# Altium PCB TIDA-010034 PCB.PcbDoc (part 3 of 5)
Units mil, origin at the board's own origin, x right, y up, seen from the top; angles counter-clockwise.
Board outline 4497.63 x 4881.81 mil, 4 copper layers (Top Layer, Signal Layer 1, Signal Layer 2, Bottom Layer), stack 62.18 mil thick; 483 components, 240 nets, 1255 pads, 589 vias.
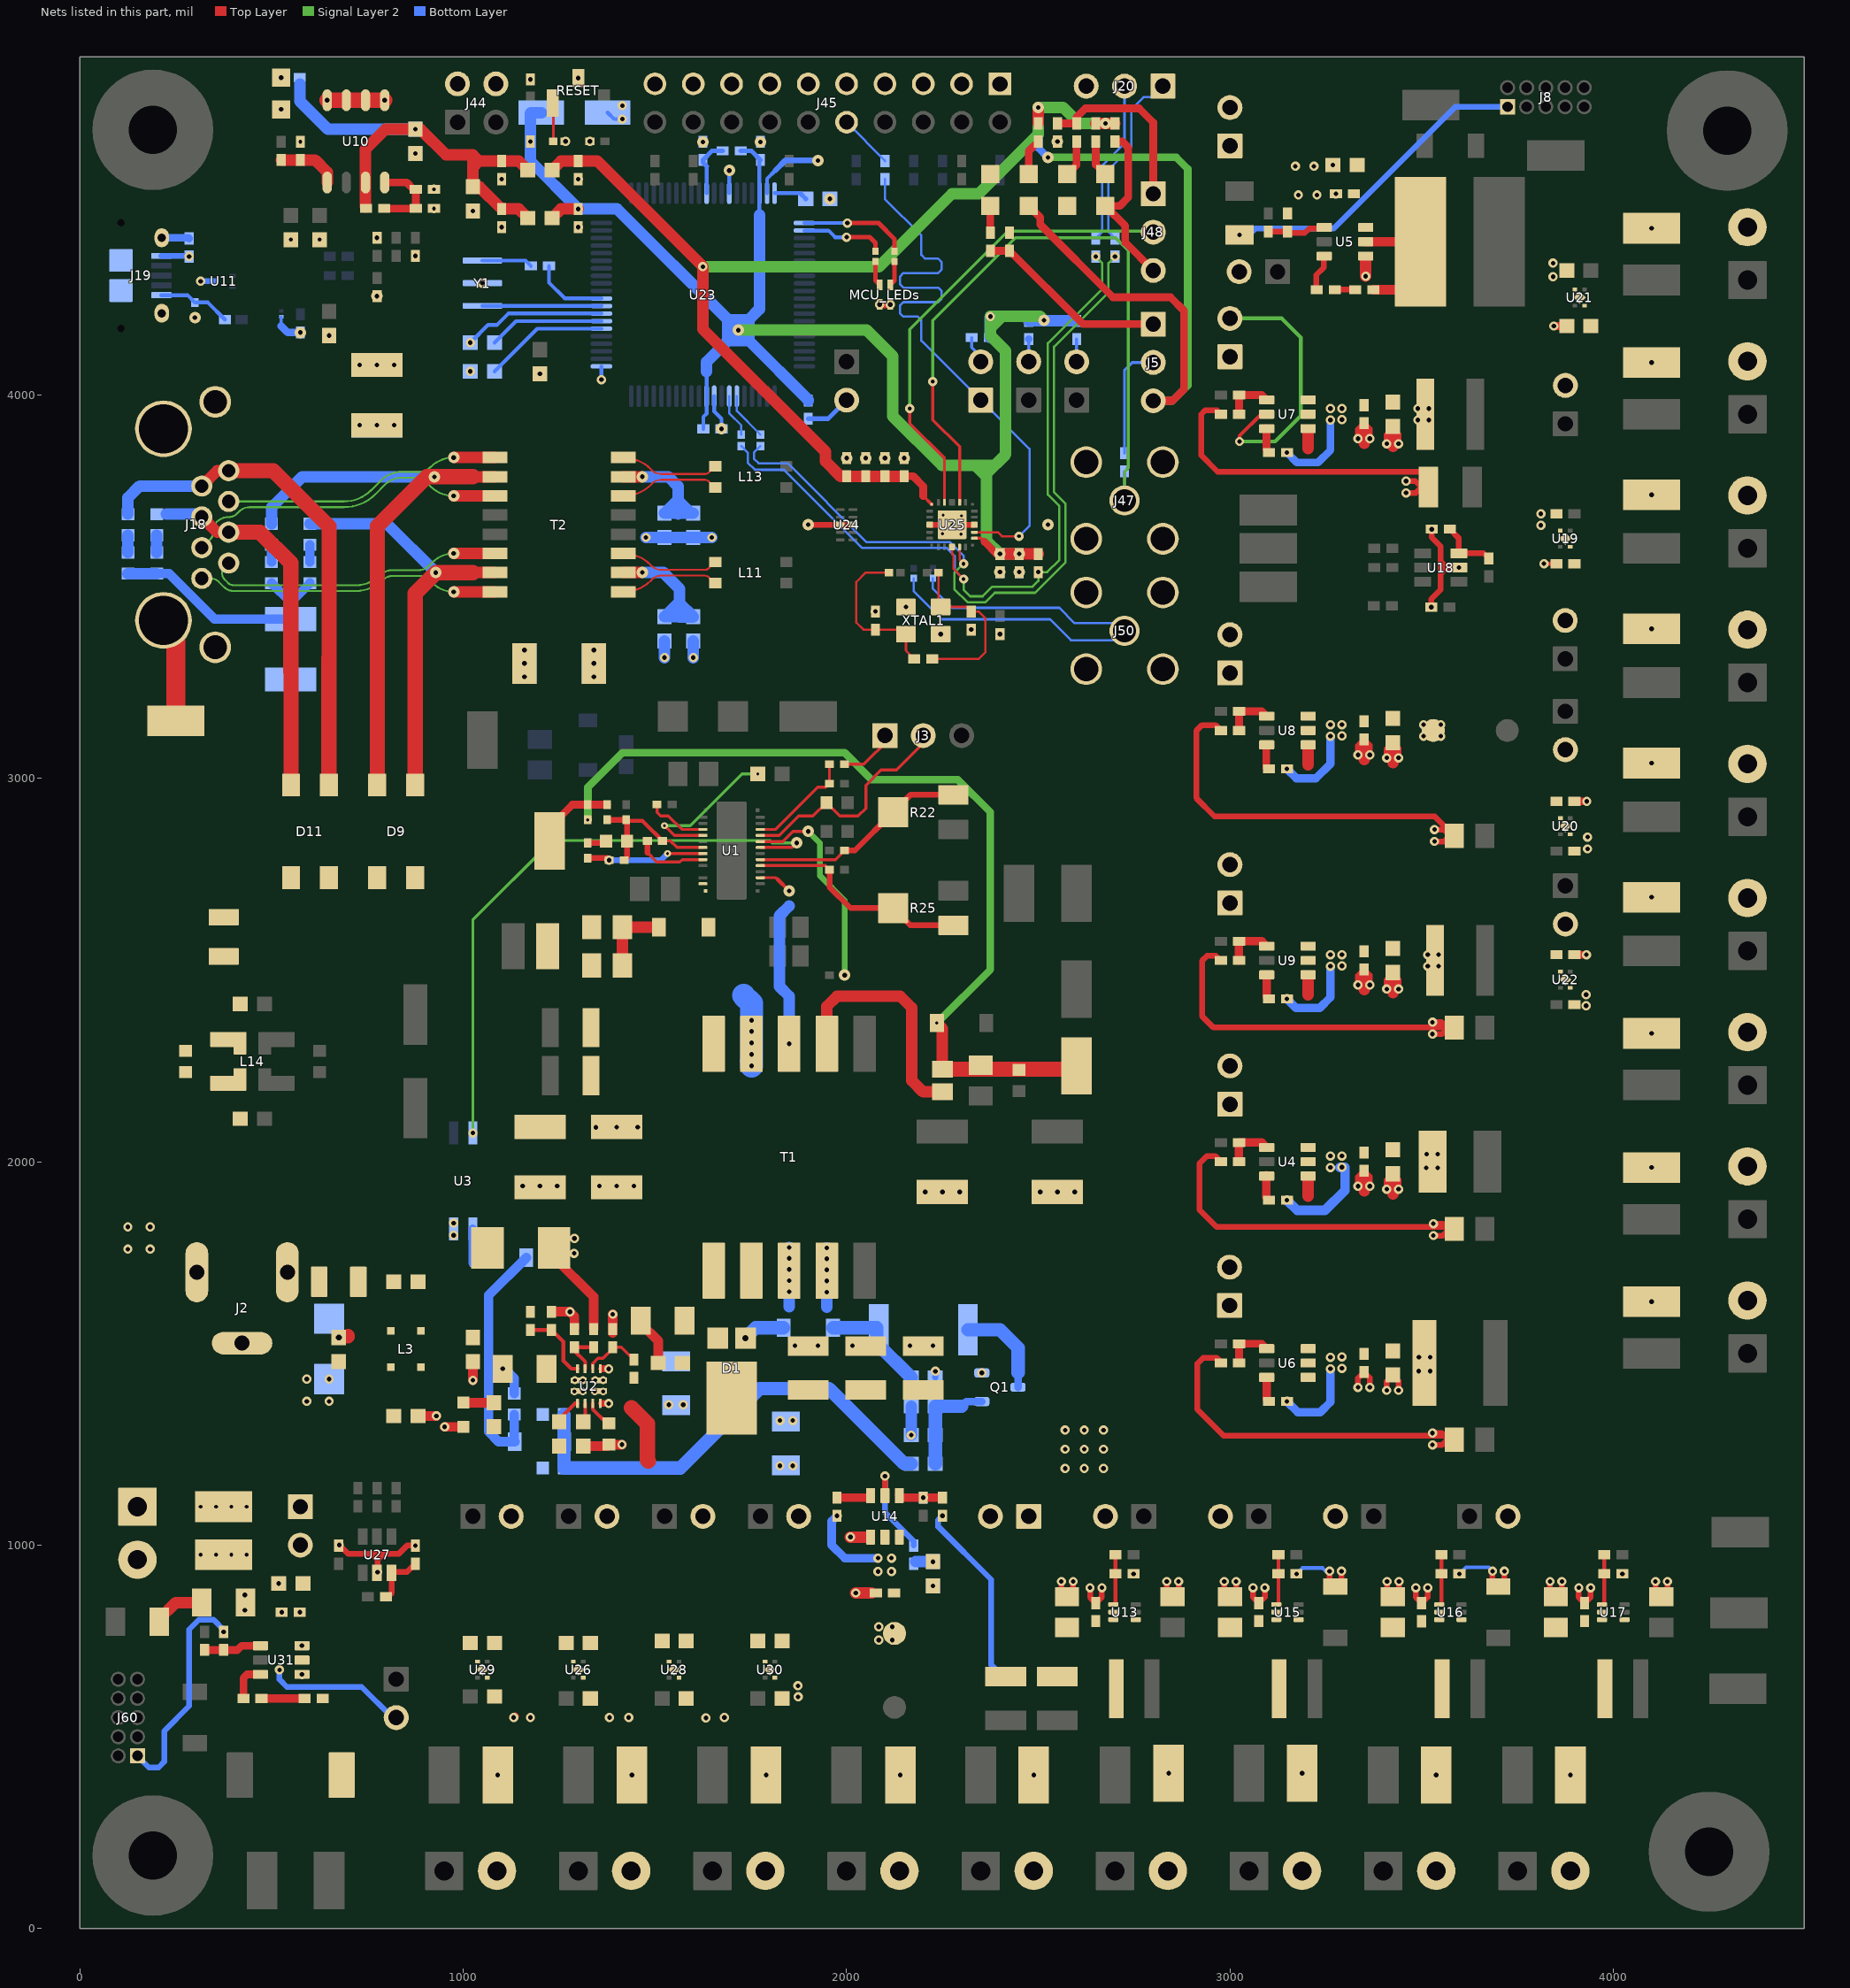
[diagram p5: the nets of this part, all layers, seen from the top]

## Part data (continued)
U2: library part CMP-0078351-3, "2.7V-22V, 4A, 50mohm Priority Power MUX, RUX0012A (VQFN-HR-12)", Alternate Manufacturer="Texas Instruments", Alternate PartNumber=TPS2121RUXT
U3: "Optocoupler, 3.75 kV, 80-160% CTR, SMT", Manufacturer="Fairchild Semiconductor", Supplier Part Number 1=HMHA2801A-ND, Voltage_Isolation_Vrms=3750V
U4: "4.5V to 17V Input, 2A Output, Synchronous SWIFT Step-Down Converter, DDC0006A (SOT-23-T-6)", Alternate Manufacturer="Texas Instruments", Alternate PartNumber=TPS562208DDCT
U5 U31: "4.5V to 28V Input Voltage, Synchronous Buck LED Driver, DDC0006A (SOT-23-T-6)", Alternate Manufacturer="Texas Instruments", Alternate PartNumber=TPS54201DDCT
U6: library part CMP-0013277-3, "4.5-V to 17-V Input, 2-A Synchronous Step-Down Voltage Regulator, DDC0006A (SOT-6)", Alternate Manufacturer="Texas Instruments", Alternate PartNumber=TPS561208DDCT
U7 U9: "4.5-V to 17-V Input, 2-A Synchronous Step-Down Voltage Regulator, DDC0006A (SOT-23-T-6)", Alternate Manufacturer="Texas Instruments", Alternate PartNumber=TPS561201DDCT
U8: "4.5V to 17V Input, 2A Output, Synchronous Step-Down Converter, DDC0006A (SOT-23-T-6)", Alternate Manufacturer="Texas Instruments"
U10: library part CMP-0036447-1, "Single Output Low Noise LDO, 500 mA, Adjustable 1.3 to 6.5 V Output, 2.5 to 16 V Input, 8-pin SOIC (D), -40 to 125 degC, Green (RoHS & no Sb/Br)", Manufacturer="Texas Instruments", Rating=Catalog
U11: "ESD Solution for Super-Speed (6 Gbps) USB 3.0 Interface, 2 Channels, -40 to +85 degC, 3-pin SOT (DRT), Green (Rohs & No Sb/Br)", Alternate Manufacturer="Texas Instruments", Alternate PartNumber=Equivalent, Breakdown Voltage(Min)(V)=9, Differential Capacitance(pF)=0.01, IO Capacitance(Typ)(pF)=0.7, IO Leakage Current(nA)=10, Supplier Part Number 1=296-25509-2-ND
U12: "ESD in 0402 Package with 10 pF Capacitance and 6 V Breakdown, 1 Channel, -40 to +125 degC, 2-pin X2SON (DPY), Green (RoHS & no Sb/Br)", Alternate Manufacturer="Texas Instruments", Alternate PartNumber=Equivalent, Breakdown Voltage(Min)(V)=6, IO Capacitance(Typ)(pF)=10, Supplier Part Number 1=296-30406-2-ND
U13 U17: "1-A High Efficiency Step-Down Converter in SOT Package, DRL0006A (SOT-OTHER-6)", Alternate Manufacturer="Texas Instruments", Alternate PartNumber=TLV62568DRLT
U14: "4.5-V TO 28-V INPUT, 2-A OUTPUT, EMI FRIENDLY SYNCHRONUOUS STEP-DOWN CONVERTOR, DDC0006A (SOT-23-T-6)", Alternate Manufacturer="Texas Instruments", Alternate PartNumber=TPS54202HDDCT
U15: library part CMP-0077789-1, "2-A High Efficiency Synchronous Buck Converter with Forced PWM Feature, DRL0006A (SOT-OTHER-6)", Alternate Manufacturer="Texas Instruments", Alternate PartNumber=TLV62569ADRLT
U16: library part CMP-0081125-1, "1-A High Efficiency Synchronous Buck Converter with Forced PWM Feature, DRL0006A (SOT-OTHER-6)", Alternate Manufacturer="Texas Instruments", Alternate PartNumber=TLV62568ADRLT
U18 U27: "Power Sequencer, 6-pin SOT-23, Pb-Free", Manufacturer="Texas Instruments", PackageTopMarking=F20A*XTT, PowerWise=N, Supplier Part Number 1=LM3880MF-1AATR-ND
U19 U26: library part CMP-0079107-2, "200-mA, Small Size, Low-Dropout Linear Voltage Regulator, DQN0004A (X2SON-4)", Alternate Manufacturer="Texas Instruments"
U20 U28: library part CMP-0079104-2, "200-mA, Small Size, Low-Dropout Linear Voltage Regulator, DQN0004A (X2SON-4)", Alternate Manufacturer="Texas Instruments"
U21 U29: library part CMP-0079101-2, "200-mA, Small Size, Low-Dropout Linear Voltage Regulator, DQN0004A (X2SON-4)", Alternate Manufacturer="Texas Instruments"
U22 U30: library part CMP-0079108-2, "200-mA, Small Size, Low-Dropout Linear Voltage Regulator, DQN0004A (X2SON-4)", Alternate Manufacturer="Texas Instruments"
U23: library part CMP-0038965-1, "25 MHz Mixed Signal Microcontroller with 128 KB Flash, 8192 B SRAM and 63 GPIOs, -40 to 85 degC, 80-pin QFP (PN), Green (RoHS & no Sb/Br)", Frequency(MHz)=25, Manufacturer="Texas Instruments", Temp Sensor=Yes
U24: library part CMP-0073613-3, "4-Channel Ultra-Low-Capacitance IEC ESD Protection Diode, DQA0010A (USON-10)", Alternate Manufacturer="Texas Instruments"
U25: library part CMP-0081932-1, "DP83825IRLLR, RLL0024A (VQFN-24)", Alternate Manufacturer="Texas Instruments", Alternate PartNumber=DP83825IRLLT
XTAL1: library part CMP-0079863-1, "Crystal, 25 MHz, 20 ppm, AEC-Q200 Grade 1, SMD", Frequency_Fixed=25MHz, Frequency Stability="50 ppm", Frequency Tolerance="20 ppm", Manufacturer="ECS Inc.", Supplier Part Number 1=XC2151CT-ND
Y1: library part CMP-0006148-5, "Resonator, 4 MHz, 1000 ppm, 39 pF, SMD", Frequency_Fixed=4MHz, Frequency Stability="800 ppm", Frequency Tolerance="1000 ppm", Load Capacitance="39 pF", Manufacturer=MuRata, Supplier Part Number 1=490-7861-1-ND
ZZ1: library part AssemblyNoteLabel
ZZ2 ZZ3 ZZ4: library part AssemblyNote

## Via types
v1: diameter 24, hole 12, Top Layer to Bottom Layer, 451 vias
v2: diameter 30, hole 12, Top Layer to Bottom Layer, 86 vias
v3: diameter 24, hole 10, Top Layer to Bottom Layer, 22 vias
v4: diameter 19.68, hole 7.87, Top Layer to Bottom Layer, 10 vias
v5: diameter 20, hole 10, Top Layer to Bottom Layer, 8 vias
v6: diameter 19.69, hole 7.87, Top Layer to Bottom Layer, 5 vias
v7: diameter 18, hole 7.5, Top Layer to Bottom Layer, 3 vias
v8: diameter 20, hole 8, Top Layer to Bottom Layer, 2 vias
v9: diameter 34, hole 16, Top Layer to Bottom Layer, 2 vias

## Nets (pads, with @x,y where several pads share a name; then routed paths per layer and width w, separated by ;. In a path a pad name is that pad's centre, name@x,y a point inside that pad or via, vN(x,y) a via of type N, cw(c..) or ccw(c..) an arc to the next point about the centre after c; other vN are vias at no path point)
3V3_IO_LDO: C73.1 C109.1 C110.2 C111.2 C117.2 C118.1 C121.1 C122.1 L17.2 R74.1 R77.1 R91.1 R106.2 R107.2 R109.2 R110.2 U23.18 U23.50 U25.19 | length 4481.7
  Top Layer w7.87: U25.19@2333.07,3626.38 2350.43,3626.38 2360,3616.81
  Top Layer w20: 2360,3616.81 2391.38,3585.43 v2(2400,3585.43)
  Top Layer w30: L17.2@1231.5,4461.81 1255.12,4485.43 v1(1300,4485.43) ; v2(2400,3585.43) v2(2450,3585.43) R91.1@2500,3585.43
  Signal Layer 2 w30: v2(1717.5,4169.31) 2052.5,4169.31 2120,4101.81 2120,3945 2248.19,3816.81 2335,3816.81 ; 2384.09,3816.81 2335,3816.81 ; v2(2450,3585.43) v2(2400,3585.43) 2365,3620.43 2365,3786.81 ; v2(2515,4195) 2505,4205 2405,4205 ; 2335,3816.81 2365,3786.81 ; 2365,3786.81 2365,3795 2415,3845 2415,4115 2375,4155 2375,4175 ; 2375,4175 v1(2375,4205) 2405,4205 ; 2375,4175 2405,4205
  Bottom Layer w10: C110.2@1626.38,3911.81 1626.38,3943.19 1634.84,3951.66 U23.50@1634.84,3997.05 1634.84,4061.66 ; 1772.64,4469.45 U23.18@1772.64,4526.58 C111.2@1772.64,4610.83
  Bottom Layer w12: R77.1@1723.62,4636.81 1751.38,4636.81 C111.2@1775,4613.19
  Bottom Layer w30: C109.1@1203.39,4736.81 1176.81,4736.81 1175,4735 v1(1175,4661.38) 1175,4610.43 v1(1300,4485.43) 1401.38,4485.43 1690,4196.81 ; 1634.84,4061.66 1634.84,4086.66 1690,4141.81 ; 1772.64,4469.45 1772.64,4224.45 1745,4196.81 ; R106.2@1900,3985.43 1900,3986.81 1745,4141.81 ; R110.2@2373.62,4150 2373.62,4203.62 v1(2375,4205) ; R109.2@2475,4193.62 R107.2@2600,4193.62 ; 1690,4141.81 v2(1717.5,4169.31) ; 1690,4141.81 1690,4196.81 ; 1690,4141.81 1745,4141.81 ; 1690,4196.81 v2@1715,4171.81 ; 1690,4196.81 1745,4196.81 ; v2@1715,4171.81 v2(1717.5,4169.31) ; v2@1715,4171.81 v2@1720,4171.81 ; v2(1717.5,4169.31) v2@1720,4171.81 ; v2(1717.5,4169.31) 1745,4141.81 ; v2@1720,4171.81 1745,4196.81 ; 1745,4141.81 1745,4196.81
3V3_VDD_LDO: C63.1 C115.2 C116.1 C119.1 C120.1 L16.2 R95.2 R96.2 R122.2 R123.2 U25.6 | length 2908.7
  Top Layer w8: 2200,3736.81 U25.6@2221.85,3714.96
  Top Layer w20: C115.2@2150,3788.19 2173.62,3788.19 2200,3761.81 2200,3736.81
  Top Layer w30: L16.2@1231.5,4586.81 1255.12,4610.43 C63.1@1300,4610.43 1349.57,4610.43 v1(1625,4335) 1625,4171.81 1945,3851.81 1945,3826.81 1983.62,3788.19 C116.1@2000,3788.19 C115.2@2150,3788.19 ; R122.2@2500,4708.62 v2(2500,4750) ; R95.2@2650,4708.62 v2(2675,4708.62) R96.2@2700,4708.62
  Signal Layer 2 w30: v1(1625,4335) 2085,4335 2275,4525 2345,4525 2500,4680 v2(2500,4750) 2565,4750 2606.38,4708.62 v2(2675,4708.62)
  Bottom Layer w30: R123.2@2500,4708.62 v2(2500,4750)
12V: 12V.1 J1.1 J4.1 J7.1 J10.1 J11.1 J14.1 J16.1 J23.1 J59.1 R4.2 R20.2 R131.2 U2.1 U2.8 | length 157.2
  Top Layer w40: 1438.87,1358 1480,1316.87 1480,1221.72 1482.72,1219
  other v1: 2570,1200 2620,1200 2670,1200 1826,1207 1859.73,1207 2570,1250 2620,1250 2670,1250 2570,1300 2620,1300 2670,1300
  other v3: 315,1100 355,1100 395,1100 435,1100
  other v5: 1290,1401 1312,1401 1343,1401 1365,1401
12V_Adapter: D5.1 R43.2 R44.2 R126.2 R132.1 U2.7 | length 254
  Top Layer w25: D5.1@1237.01,1775 1237.01,1750.49 1340,1647.5 R43.2@1340,1563.62
  other v1: 1289,1761 1289.76,1800
  other v5: 1291,1430 1312,1430
12V_PoE: C7.1 C8.1 C9.1 C10.1 D1.3 R128.2 R131.1 R132.2 U2.2
  other v1: 1826.29,1325 1859.73,1325 1536,1366 1574,1366
  other v5: 1344,1430 1365,1430
AUX_D: U1.7 U3.4 | length 1589.5
  Top Layer w7.8: U1.7@1774.8,2819.69 1857.87,2819.69 v2(1870,2831.81)
  Signal Layer 2 w7.8: v1(1025,2075) 1025,2631 1232,2838 1800,2838 1806.19,2831.81 v2(1870,2831.81)
Aux_Detect: C26.1 D7.1 R7.2 R29.2 | length 1210.4
  Bottom Layer w35: R29.2@1262.56,1201 1566,1201 1773,1408 1954,1408 2150.19,1211.81 R7.2@2168.5,1211.81 ; R29.2@1262.56,1203 C26.1@1262.56,1340.44
CLK_OUT: J47.1 R94.2 U25.2 | length 1849.1
  Top Layer w7.87: U25.2@2294.69,3719.88 2294.69,3865.31
  Top Layer w8: v3(2225,4035) 2225,3935 2294.69,3865.31
  Signal Layer 2 w7.87: v3(2225,4035) 2225,4195 2440,4410 2701.81,4410 2735,4376.81 2735,3810 2725,3800 J47.1@2725,3725
  Bottom Layer w7.87: J47.1@2725,3725 R94.2@2725,3801.38
CP: R19.2 T1.3 | length 380.3
  Bottom Layer w30: v2(1850,2307.58) 1850,2431.81 1825,2456.81 1825,2642.13 R19.2@1850,2667.13
CRS_DV: J53.1 R84.2 U25.20 | length 1601.1
  Top Layer w6: U25.20@2333.07,3642.13 2394.68,3642.13 2405,3631.81 v3(2450,3631.81)
  Bottom Layer w6: R84.2@2100,4563.19 2100,4511.81 2195,4416.81 2195,4375 2195,4365.53 2204.47,4356.06 2238.59,4356.06 2248.06,4346.59 2248.06,4327.66 2238.59,4318.19 2195,4318.19 2148.41,4318.19 2138.94,4308.72 2138.94,4289.78 2148.41,4280.31 2195,4280.31 2238.59,4280.31 2248.06,4270.85 2248.06,4251.91 2238.59,4242.44 2195,4242.44 2148.41,4242.44 2138.94,4232.97 2138.94,4214.04 2148.41,4204.57 2185.53,4204.57 2195,4195.1 2195,4178.94 2195,4141.81 J53.1@2350,3986.81 2477.19,3859.62 2477.19,3659 v3(2450,3631.81)
CRS_DV_S: J45.10 R84.1 | length 142.8
  Bottom Layer w6: J45.10@2000,4711.81 2100,4611.81 R84.1@2100,4610.43
DRAIN: D2.2 T1.1 U1.24 U1.A4
EARTH_GND: C57.1 C125.2 C126.2 EARTH.1 J18.9 J18.10 J18.11 J18.12 R101.1 R102.1 | length 278.5
  Top Layer w50: J18.11@217.91,3412.2 250,3380.12 EARTH.1@250,3147
  other v1: 1159.45,3265 1159.45,3300 1159.45,3335 730,3921.26 775,3921.26 820,3921.26
EXT_REF_CLK: J50.1 R108.1 R124.1 | length 1218.9
  Bottom Layer w6: R124.1@2175,3522.01 2175,3488.83 2248.83,3415 2531,3415 2585.37,3360.63 2700.63,3360.63 J50.1@2725,3385 2705,3405 2595,3405 2555,3445 2275,3445 2225,3495 R108.1@2225,3522.01
GND: +3.3V.2 +12V_PoE.1 C1.2 C2.2 C7.2 C8.2 C9.2 C12.1 C15.2 C20.2 C22.2 C26.2 C27.2 C28.2 C31.2 C33.2 C34.2 C35.2 C36.2 C37.2 C40.2 C41.2 C42.2 C43.2 C44.2 C45.2 C47.2 C48.2 C49.2 C51.2 C52.2 C53.2 C56.2 C62.2 C63.2 C64.2 C65.2 C66.2 C67.2 C68.2 C69.2 C70.2 C71.2 C72.2 C73.2 C74.2 C75.2 C77.2 C79.2 C80.2 C81.2 C82.2 C83.2 C84.2 C85.2 C86.2 C87.2 C88.2 C89.2 C90.2 C91.2 C92.2 C93.2 C94.2 C95.2 C96.2 C97.2 C98.2 C99.2 C100.2 C101.2 C102.2 C103.2 C104.1 C105.2 C106.2 C107.1 C108.2 C109.2 C110.1 C111.1 C112.1 C113.2 C114.2 C115.1 C116.2 C117.1 C118.2 C119.2 C120.2 C121.2 C122.2 C123.1 C124.1 C125.1 C126.1 C127.2 C128.2 C129.2 C130.2 C131.2 C132.2 C133.2 C134.2 C135.2 C136.2 C139.2 C140.2 C141.2 C142.2 D13.2 GND.1 J1.2 J6.2 J8.1 J9.2 J12.2 J13.2 J15.2 J17.2 J19.5 J20.3 J24.2 J25.2 J27.2 J29.2 J31.2 J34.2 J36.2 J39.2 J40.2 J43.2 J44.2 J44.4 J45.1 J45.3 J45.5 J45.7 J45.9 J45.11 J45.13 J45.15 J45.17 J45.19 J47.2 J47.3 J47.4 J47.5 J50.2 J50.3 J50.4 J50.5 J54.2 J55.2 J57.2 J58.2 J60.1 L3.2 L4.2 LED0_H.2 LED2_H.2 MCU_LEDs.3 MCU_LEDs.4 Q1.2 R9.1 R29.1 R32.1 R34.1 R37.1 R38.1 R40.1 R42.1 R52.1 R53.1 R54.2 R58.1 R59.1 R61.1 R63.1 R65.1 R76.2 R92.2 R93.1 R98.1 R101.2 R102.2 R103.1 R112.1 R117.1 R121.2 R125.1 R127.1 R129.1 R130.1 RESET.3 T1.7 T1.8 U2.3 U2.12 U3.2 U4.1 U5.1 U6.1 U7.1 U8.1 U9.1 U10.5 U10.6 U10.7 U10.8 U11.3 U12.2 U13.2 U14.1 U15.2 U16.2 U17.2 U18.2 U19.2 U19.5 U20.2 U20.5 U21.2 U21.5 U22.2 U22.5 U23.14 U23.19 U23.49 U23.61 U23.68 U24.3@2016.44,3661.81 U24.8@1983.56,3661.81 U25.9 U25.21 U25.25 U26.2 U26.5 U27.2 U28.2 U28.5 U29.2 U29.5 U30.2 U30.5 U31.1 XTAL1.2 XTAL1.4 Y1.2 | length 13439.1
  Top Layer w10: v1@3819.24,3560 C97.2@3851.38,3560
  Top Layer w12: U2.12@1357.4,1369.41 1362.87,1369.41 ; U2.3@1357.4,1459.96 1362.87,1459.96
  Top Layer w15: v1(676.38,1000.43) 700,976.81 761.38,976.81 ; v1(776.38,929.57) 776.38,961.81 ; v1(875,998.62) 853.19,998.62 831.38,976.81 791.38,976.81 ; v2(1900,3661.81) U24.8@1983.56,3661.81 U24.3@2016.44,3661.81 ; U25.9@2216.93,3661.81 v6(2275,3661.81) U25.21@2333.07,3661.81 ; v1(2560,905) 2560,880 C79.2@2575,865 2591,881 v1(2591,905) ; v1(2635,888.62) 2635,863.62 C80.2@2650,848.62 2666,864.62 v1(2666,888.62) ; v1(2835,905) 2835,880 C77.2@2850,865 2866,881 v1(2866,905) ; R37.1@2976.38,1475 2976.38,1477.62 2966,1488 2930,1488 2915,1473 2915,1354 2984,1285 3559.7,1285 ; R32.1@2976.38,2000 2961.38,2015 2940,2015 2920,1995 2920,1875 2965,1830 C31.2@3563.09,1830 ; R42.1@2976.38,2525 2975,2525 2963,2537 2940,2537 2927,2524 2927,2380 2957,2350 C51.2@3566.3,2350 ; R40.1@2976.38,3125 2962.38,3139 2927,3139 2912,3124 2912,2949 2960,2901 3534,2901 C47.2@3585,2850 ; R38.1@2976.38,3950 2966.38,3960 2935,3960 2925,3950 2925,3843 2968,3800 C43.2@3500,3800 ; v1(2985,905) 2985,880 C87.2@3000,865 3016,881 v1(3016,905) ; v1(3060,888.62) 3060,863.62 C88.2@3075,848.62 3091,864.62 v1(3091,888.62) ; v1(3260,931.93) 3260,906.93 C86.2@3275,891.93 3291,907.93 v1(3291,931.93) ; v1(3334,1411.38) 3334,1435.38 C42.2@3350,1451.38 3365,1436.38 v1(3365,1411.38) ; v1(3334,1936.38) 3334,1960.38 C34.2@3350,1976.38 3365,1961.38 v1(3365,1936.38) ; v1(3334,2461.38) 3334,2485.38 C53.2@3350,2501.38 3365,2486.38 v1(3365,2461.38) ; v1(3334,3061.38) 3334,3085.38 C49.2@3350,3101.38 3365,3086.38 v1(3365,3061.38) ; v1(3334,3886.38) 3334,3910.38 C45.2@3350,3926.38 3365,3911.38 v1(3365,3886.38) ; v1(3409,1403.5) 3409,1427.5 C41.2@3425,1443.5 3440,1428.5 v1(3440,1403.5) ; v1(3409,1928.5) 3409,1952.5 C33.2@3425,1968.5 3440,1953.5 v1(3440,1928.5) ; v1(3409,2450.57) 3409,2474.57 3425,2490.57 3440,2475.57 v1(3440,2450.57) ; v1(3409,3053.5) 3409,3077.5 C48.2@3425,3093.5 3440,3078.5 v1(3440,3053.5) ; v1(3409,3872.77) 3409,3896.77 3425,3912.77 3440,3897.77 v1(3440,3872.77) ; v1(3410,905) 3410,880 C90.2@3425,865 3441,881 v1(3441,905) ; v1(3459.61,3744.8) 3484.61,3744.8 3499.61,3759.8 3483.61,3775.8 v1(3459.61,3775.8) ; v1(3485,888.62) 3485,863.62 C91.2@3500,848.62 3516,864.62 v1(3516,888.62) ; C43.2@3500,3785 3517.91,3767.09 C43.2@3517.91,3760 ; v1(3525.39,3446.81) 3525.39,3467.98 3550,3492.58 3550,3535 ; v1(3526.38,3650) 3526.38,3628.62 3550,3605 3550,3565 ; v1(3528.3,2333) 3553.3,2333 3568.3,2348 C51.2@3566.3,2350 ; v1(3528.3,2364) 3552.3,2364 C51.2@3566.3,2350 ; v1(3528.36,1261.33) 3553.36,1261.33 3568.36,1276.33 3559.7,1285 ; v1(3528.36,1292.33) 3552.36,1292.33 3559.7,1285 ; v1(3530.67,1807.42) 3555.67,1807.42 3570.67,1822.42 C31.2@3563.09,1830 ; v1(3530.67,1838.42) 3554.67,1838.42 C31.2@3563.09,1830 ; v1(3533.62,2835.59) 3558.62,2835.59 3573.62,2850.59 3557.62,2866.59 v1(3533.62,2866.59) ; C40.2@3585,1275 3580,1275 3570,1285 3559.7,1285 ; C31.2@3585,1825 3585,1840 3575,1830 C31.2@3563.09,1830 ; C51.2@3585,2350 C51.2@3566.3,2350 ; v1(3597.24,3550) 3565,3550 ; v1(3685,931.93) 3685,906.93 C89.2@3700,891.93 3716,907.93 v1(3716,931.93) ; v1(3835,905) 3835,880 C93.2@3850,865 3866,881 v1(3866,905) ; v1(3910,888.62) 3910,863.62 C94.2@3925,848.62 3941,864.62 v1(3941,888.62) ; v1(4110,905) 4110,880 C92.2@4125,865 4141,881 v1(4141,905) ; 761.38,976.81 776.38,961.81 ; 761.38,976.81 791.38,976.81 ; 776.38,961.81 791.38,976.81 ; 3550,3535 3550,3565 ; 3550,3535 3565,3550 ; 3550,3565 3565,3550
  Top Layer w18: 1362.87,1369.41 1379.09,1369.41 v1(1379.37,1369.14) ; 1362.87,1459.96 1379.09,1459.96 v1(1379.37,1459.69)
  Top Layer w20: v1(1131.5,550) v1@1135,553.5 ; U14.1@2051.13,1020.87 U14.1@2062.6,1020.87 ; C85.2@2064.91,875 C85.2@2076.38,875 ; v1(2086.22,4236.22) v1(2113.78,4236.22) ; U4.1@3204.13,1951.13 U4.1@3204.13,1962.6 ; U9.1@3204.13,2476.13 U9.1@3204.13,2487.6 ; U8.1@3204.13,3076.13 U8.1@3204.13,3087.6 ; U7.1@3204.13,3901.13 U7.1@3204.13,3912.6 ; C34.2@3350,1964.91 C34.2@3350,1976.38 ; C53.2@3350,2489.91 C53.2@3350,2501.38 ; C49.2@3350,3089.91 C49.2@3350,3101.38 ; C45.2@3350,3914.91 C45.2@3350,3926.38 ; U5.1@3354.13,4351.13 U5.1@3354.13,4362.6 ; C33.2@3425,1957.04 C33.2@3425,1968.5 ; C52.2@3425,2482.04 3425,2490.57 C52.2@3425,2493.5 ; C48.2@3425,3082.04 C48.2@3425,3093.5 ; C44.2@3425,3907.04 3425,3912.77 C44.2@3425,3918.5 ; v1(3819.17,3560.06) v1@3819.24,3560 ; v1(3845,4180) C101.2@3877.14,4180 ; C103.2@3898.62,2540 v1(3930,2540) ; C100.2@3898.62,2940 v1@3930.76,2940
  Top Layer w25: L4.2@881.5,1336.81 v1(930,1336.81) ; v1(951.5,1308.5) +12V_PoE.1@1000,1308.5 ; v1(1025,1430) C20.2@1025,1478.5 ; R129.1@1230,1608.62 v1(1278.5,1608.62) 1278.5,1607.5 1290,1596 R125.1@1290,1563.62 ; R127.1@1315,1258.5 1376.06,1258.5 C22.2@1380,1262.44 1380.44,1262 v1(1414,1262) ; R130.1@1390,1553.62 v1(1390,1602.13)
  Top Layer w30: v1(2010,1021) 2051,1021 U14.1@2051.13,1020.87 ; v1(2023.78,875.13) 2064.78,875.13 C85.2@2064.91,875 ; 3204,1910 3204,1951 U4.1@3204.13,1951.13 ; 3204,2435 3204,2476 U9.1@3204.13,2476.13 ; 3204,3035 3204,3076 U8.1@3204.13,3076.13 ; 3204,3860 3204,3901 U7.1@3204.13,3901.13 ; 3349.87,1923.78 3349.87,1964.78 C34.2@3350,1964.91 ; 3349.87,2448.78 3349.87,2489.78 C53.2@3350,2489.91 ; 3349.87,3048.78 3349.87,3089.78 C49.2@3350,3089.91 ; 3349.87,3873.78 3349.87,3914.78 C45.2@3350,3914.91 ; v1(3354,4310) 3354,4351 U5.1@3354.13,4351.13 ; 3424.87,1915.91 3424.87,1956.91 C33.2@3425,1957.04 ; 3424.87,2440.91 3424.87,2481.91 C52.2@3425,2482.04 ; 3424.87,3040.91 3424.87,3081.91 C48.2@3425,3082.04 ; 3424.87,3865.91 3424.87,3906.91 C44.2@3425,3907.04
  Top Layer w40: v1(645,4769.09) U10.7@695,4769.09 U10.6@745,4769.09 v1(795,4769.09)
  Bottom Layer w8: 525,4180 D13.2@525,4204.33
  Bottom Layer w10: v1(1018.5,4136.81) 1065,4183.31 1088.31,4183.31 1117.6,4212.6 U23.68@1360.24,4212.6 ; v1(1360.24,4040.24) U23.61@1360.24,4074.81 ; C109.2@1376.61,4736.81 1393.43,4720 v1(1415,4720) ; U23.49@1654.53,3997.05 1654.53,3957.28 1673.62,3938.19 v2(1673.62,3911.81) ; U23.14@1693.9,4526.58 v2(1693.9,4585.71) ; U23.19@1792.32,4526.58 1792.32,4564.14 1815,4586.81 ; v1(3173.62,925) 3188.62,940 3242,940 3250.07,931.93 v1(3260,931.93) ; v1(3598.62,925) 3615.63,942 3674.93,942 v1(3685,931.93)
  Bottom Layer w15: J60.1@150,450 179.92,420.08 204.92,420.08 220,435.16 220,515 285,580 285,780 310,805 348.74,805 375,778.74 v1(375,773.62) ; J19.5@212.4,4362.99 283.39,4362.99 v1(285,4361.38) ; v1(315,4296.81) U11.3@352.36,4296.81 ; v1(520.63,674.41) 520.63,649.33 539.96,630 735,630 815,550 J58.2@825,550 ; 1815,4586.81 1840,4611.81 v2(1925,4611.81) ; C12.1@2230,1438.31 C12.1@2231.5,1436.81 v1(2231.5,1453.5) ; v1(2250,1076.38) 2239,1065.38 2239,1048 2377,910 2377,688 2405,660 ; v1(3025,4417.91) 3050,4417.91 3066.09,4434 3270,4434 3587.81,4751.81 J8.1@3724.02,4751.81
  Bottom Layer w20: 525,4180 541.81,4163.19 v2(575,4163.19) ; v1(2140,400) 2140,434
  Bottom Layer w30: v1(1476.5,3628.5) C56.2@1525,3628.5 C74.2@1600,3628.5 v1(1648.5,3628.5) ; v1(1525,3315) C75.2@1525,3358.5 ; v1(1600,3315) C142.2@1600,3358.5 ; 1850,1621.58 v1(1850,1661) v1(1850,1690) v1(1850,1719) v1(1850,1748) v1(1850,1776) ; 1948,1620.3 v1(1948,1660) v1(1948,1689) v1(1948,1718) v1(1948,1747) v1(1948,1775) ; v1(2168.5,1286.81) R9.1@2168.5,1361.81
  other v1: 1090,400 1440,400 1790,400 2488,400 3538,400 3888,400 2840,405 3188,405 1633,549 1175,550 1381.5,550 1431.5,550 1681,550 1873.51,604 1873.14,633 579.13,662.6 526.38,825 430,830 430,870 2225,893.5 518.5,900 2748.62,925 4023.62,925 2352.76,1449.21 1865,1520 1925,1520 2015,1520 2165,1520 2225,1520 4100,1635 975,1808.27 975,1840 2205,1921.26 2250,1921.26 2295,1921.26 2505,1921.26 2550,1921.26 2595,1921.26 4100,1985 4100,2335 3929,2407 3929,2436 4100,2690 3933,2816 3933,2847 3930.83,2939.94 4100,3040 1340.55,3265 1340.55,3300 1340.55,3335 2400,3376.38 2325,3388.19 4100,3390 2075,3435.43 3811,3660 3811,3690 4100,3740 1018.5,4061.81 730,4078.74 775,4078.74 820,4078.74 4100,4085 1050,4291.81 3842.87,4308.57 3842.94,4344.06 875,4363.19 775,4410.43 4100,4435 1100,4438.19 1300,4438.19 1025,4480.32 3178.39,4521.81 3226.89,4521.81 3276.38,4525 1100,4563.19 1300,4563.19 3170.51,4596.81 3219.02,4596.81 3268.5,4600 875,4630.32 1266.96,4661.81 1330.32,4661.81 525,4745.47 1415,4755 1175,4823.62 1300,4826.77
  other v2: 1155,1936.81 1200,1936.81 1245,1936.81 1355,1937.01 1400,1937.01 1445,1937.01 2245.28,3376.38 2154.72,3447.24 2400,3538.19 2450,3538.19 2525,3661.81 2000,3835.43 2050,3835.43 2100,3835.43 2150,3835.43 1200,4055.32 650,4155.32 300,4202.13 775,4258.19 1956.5,4511.81 1625,4660.44 1775,4660.44 2550,4661.38
  other v3: 315,975 355,975 395,975 435,975 550,4405.32 625,4405.32 923.62,4486.81 923.62,4536.81 575,4660.43
  other v6: 2298.19,3636.81 2250,3638.62 2300,3685 2251.81,3686.81
LED_0: J48.2 U25.4 | length 1231.2
  Top Layer w7.87: v3(2165,3965) 2165,3925.32 2255.32,3835 U25.4@2255.32,3719.88
  Signal Layer 2 w7.87: v3(2165,3965) 2165,4171.81 2420.59,4427.41 2797.59,4427.41 J48.2@2800,4425
LED_2: J5.2 R94.1 | length 299.7
  Bottom Layer w7.87: R94.1@2725,3848.62 2725,4065 2745,4085 J5.2@2800,4085
MDC: R71.1 R89.1 U25.16 | length 2060.5
  Top Layer w6: U25.16@2294.69,3603.74 2294.69,3570.31 v3(2305,3560)
  Signal Layer 2 w6: v3(2305,3560) 2281.13,3536.13 2281.13,3493.87 2315.87,3459.13 2361.58,3459.13 2386.58,3484.13 2491.58,3484.13 2570.87,3563.42 2570.87,3716.58 2540.87,3746.58 2540.87,4125.87 2683,4268 2683,4344.38 v1(2700,4361.38)
  Bottom Layer w6: R71.1@1775,3866.85 1774.85,3866.85 1758,3850 1758,3833.81 1770,3821.81 1846.19,3821.81 2052,3616 2270,3616 2305,3581 v3(2305,3560)
MDC_EXT: J20.1 R89.2 | length 473.6
  Bottom Layer w6: R89.2@2700,4408.62 2683,4425.62 2683,4588 2743,4648 2743,4746 2774,4777 2802,4777 J20.1@2825,4800
MDC_OB: R71.2 U23.46 | length 125.7
  Bottom Layer w6: U23.46@1713.58,3997.05 1713.58,3958.19 R71.2@1775,3896.77
MDIO: R72.1 R90.1 R91.2 U25.15 | length 2064
  Top Layer w6: U25.15@2275,3603.74 2275,3585 2278.94,3581.06 2278.94,3546.06 v3(2305,3520)
  Signal Layer 2 w6: v3(2305,3520) 2305,3492.45 2322.45,3475 2355,3475 2380,3500 2485,3500 2500,3515 v1(2500,3538.19) 2523.19,3538.19 2555,3570 2555,3710 2525,3740 2525,4135 2667,4277 2667,4344.38 v1(2650,4361.38)
  Bottom Layer w6: R72.1@1725,3866.85 1742,3849.85 1742,3824 1761,3805 1836.81,3805 2040.81,3601 2261,3601 2282,3580 2282,3543 v3(2305,3520)
MDIO_EXT: J20.2 R90.2 | length 422.4
  Bottom Layer w6: R90.2@2650,4408.62 2667,4425.62 2667,4599 2725,4657 J20.2@2725,4800
MDIO_OB: R72.2 U23.47 | length 113.2
  Bottom Layer w6: U23.47@1693.9,3997.05 1693.9,3952.1 1725,3921 R72.2@1725,3896.77
MSP_XIN2: U23.69 Y1.3 | length 310.2
  Bottom Layer w10: Y1.3@1050,4232.29 U23.69@1360.24,4232.29
MSP_XOUT2: R73.2 U23.70 | length 197.3
  Bottom Layer w10: R73.2@1223.62,4336.81 1223.62,4293.19 1264.84,4251.97 U23.70@1360.24,4251.97
Net+3.3V_1: +3.3V.1 R51.1
  other v1: 525,4828.15
Net+12V_PoE_2: +12V_PoE.2 R4.1 | length 80
  Top Layer w25: +12V_PoE.2@1000,1371.5 R4.1@1080,1371.5
NetC1_1: C1.1 C2.1 C3.1 C5.1 C6.1 L1.2 R1.2 T1.2 | length 194
  Bottom Layer w60: 1731,2434 1751.58,2413.42 1751,2412.85 1752,2411.85 v1(1752,2369) v1(1752,2340) v1(1752,2310) v1(1752,2280) 1752,2263.73 1751,2262.73 1752,2261.73 v1(1752,2250)
  other v1: 1345.84,2089.42 1400,2090.55 1455,2090.44
NetC3_2: C3.2 D2.1 R1.1 | length 195.5
  Top Layer w30: C3.2@1415,2511.81 R1.1@1415,2611.81 D2.1@1510.53,2611.81
NetC10_2: C10.2 R2.2 | length 128.9
  Top Layer w25: R2.2@1462.91,1585 1462.91,1578.09 1508.5,1532.5 C10.2@1508.5,1475
NetC11_1: C11.1 D4.2 R3.1 R5.2 R14.2 VBIAS.1 | length 2324
  Top Layer w30: v8(2235.53,2361.81) 2250,2347.34 R3.1@2250,2241.34
  Top Layer w40: R3.1@2250,2241.34 2591.34,2241.34 VBIAS.1@2600,2250
  Signal Layer 2 w20: v8(1325,2892.13) 1325,2976.81 1415,3066.81 1995,3066.81 2065,2996.81 2290,2996.81 2375,2911.81 2375,2501.28 v8(2235.53,2361.81)
NetC12_2: C12.2 D3.1 R6.2 | length 281.5
  Bottom Layer w35: D3.1@1964.47,1566.81 2078.86,1566.81 2078.86,1526.46 C12.2@2168.5,1436.81
NetC15_1: C15.1 Q1.1 R7.1 R9.2 | length 305
  Bottom Layer w20: 2300,1361.81 2312.6,1374.41 Q1.1@2352.76,1374.41
  Bottom Layer w35: R7.1@2231.5,1211.81 C15.1@2231.5,1286.81 ; 2231.5,1258.31 R9.2@2231.5,1361.81 2300,1361.81
NetC17_1: C17.1 R16.2 U1.19 | length 309.5
  Top Layer w7.8: v7(1532.87,2803.94) U1.19@1625.2,2803.94
  Top Layer w15: R16.2@1325,2792.13 1375,2792.13 v1(1380.32,2786.81)
  Bottom Layer w15: v1(1380.32,2786.81) 1515.75,2786.81 v7(1532.87,2803.94)
NetC17_2: C17.2 C18.2 R15.1 R18.2 R21.2 U1.18 | length 386.5
  Top Layer w7.8: R18.2@1519.69,2836.81 1540,2836.81 1557.13,2819.69 U1.18@1625.2,2819.69
  Top Layer w10: R21.2@1427.56,2889.57 1467.24,2889.57 1497.28,2859.53 1497.46,2859.53 1519.69,2837.3 R18.2@1519.69,2836.81
  Top Layer w15: R15.1@1375,2892.13 R21.2@1425,2892.13 1427.56,2889.57 C18.2@1427.56,2836.81 1427.56,2794.69 C17.2@1419.69,2786.81
NetC18_1: C18.1 R16.1 | length 49.6
  Top Layer w15: R16.1@1325,2831.5 1367.13,2831.5 C18.1@1372.44,2836.81
NetC19_1: C19.1 D14.2 F1.1 L2.1 L3.4 | length 2.9
  Top Layer w35: 700,1543.31 700,1546.24
  other v9: 675,1541.5
NetC19_2: C19.2 D14.1 J2.2 J2.3 L3.1 L4.1
  other v1: 591.93,1375 650,1375 591.93,1433.07 650,1433.07 125,1771.93 183.07,1771.93 125,1830 183.07,1830
NetC20_1: C20.1 D5.2 L2.2 L3.3 R27.2 R126.1 | length 79.9
  Bottom Layer w25: v1(1102.91,1460) 1108,1460 1133.07,1434.93 R27.2@1133.07,1395.56
NetC22_1: C22.1 U2.11 | length 72.6
  Top Layer w10: U2.11@1337.72,1369.41 1337.72,1354.28 1374.44,1317.56 C22.1@1380,1317.56
NetC24_1: C24.1 J3.2 U1.9 | length 603.2
  Top Layer w7.8: U1.9@1774.8,2851.18 1824.37,2851.18 1875,2901.81 1912.44,2901.81 C24.1@1947.44,2936.81 1982.44,2901.81 2030,2901.81 2050,2921.81 2050,2981.81 2090,3021.81 2130,3021.81 J3.2@2210,3101.81
NetC29_1: C29.1 L5.1 U4.2 | length 257.1
  Bottom Layer w25: v1(3148.62,1900) 3175.62,1873 3248,1873 3300,1925 3300,1985 v1@3287,1985
  other v1: 3512,1984 3542,1984 3262,1985 3292,1986 3262,2015 3292,2015 3513,2020 3542,2020
NetC29_2: C29.2 U4.6 | length 66.3
  Top Layer w22: U4.6@3094.88,1964.41 U4.6@3094.88,1961.61 ; U4.6@3095.87,1962.6 U4.6@3094.88,1961.61 ; C29.2@3100.39,1901.81 3094.88,1907.32 U4.6@3094.88,1961.61
NetC30_1: C30.1 R31.1 | length 52.8
  Top Layer w15: C30.1@3273.62,4275 R31.1@3326.38,4275
NetC30_2: C30.2 U5.6 | length 95.7
  Top Layer w15: C30.2@3225.39,4271.81 3225.39,4313.19 3244.88,4332.68 U5.6@3244.88,4359.41
NetC33_1: C33.1 C34.1 J4.2 U4.3
NetC35_1: C35.1 C36.1 J7.2 U5.3
NetC37_1: C37.1 R33.1 U5.4 | length 150.4
  Top Layer w15: R33.1@3100,4426.38 C37.1@3150,4426.38 ; C37.1@3149.02,4423.19 3195.39,4423.19 3206.42,4434.21 U5.4@3244.88,4434.21
NetC38_1: C38.1 L7.1 U6.2 | length 222.7
  Bottom Layer w22: v1(3148.62,1375) 3176.62,1347 3236,1347 3262,1373 v1(3262,1460)
  other v1: 3492,1454 3522,1454 3292,1461 3262,1490 3493,1490 3522,1490 3292,1491
NetC38_2: C38.2 U6.6 | length 64.9
  Top Layer w22: U6.6@3095.87,1437.6 3095.87,1380.51 C38.2@3101.38,1375
NetC39_1: C39.1 L8.1 U7.2 | length 216.4
  Bottom Layer w20: v1(3148.62,3850) 3174.62,3824 3230,3824 3262,3856 v1(3262,3935)
  other v1: 3490,3935 3519,3935 3292,3936 3262,3965 3292,3965 3490,3965 3519,3965
NetC39_2: C39.2 U7.6 | length 120.6
  Top Layer w20: U7.6@3094.88,3914.41 C39.2@3094.88,3857.32 ; U7.6@3095.87,3912.6 3095.87,3858.31 C39.2@3094.88,3857.32 ; C39.2@3100.39,3851.81 C39.2@3094.88,3857.32
NetC41_1: C41.1 C42.1 J10.2 U6.3
NetC44_1: C44.1 C45.1 J11.2 U7.3 U7.5 | length 709.3
  Top Layer w10: v1@3025,3876 v1(3025,3879) 3025,3893.63 3081.37,3950 U7.5@3095.87,3950
  Signal Layer 2 w10: J11.2@3000,4200 3135,4200 3185,4150 3185,3946 3118,3879 v1(3025,3879)
NetC46_1: C46.1 L9.1 U8.2 | length 211.5
  Bottom Layer w22: v1(3148.62,3025) 3173.62,3000 3224,3000 3262,3038 v1(3262,3110)
  other v1: 3505,3110 3550,3110 3292,3111 3262,3140 3292,3140 3505,3140 3550,3140
NetC46_2: C46.2 U8.6 | length 57.1
  Top Layer w20: C46.2@3094.88,3027.32 U8.6@3094.88,3084.41
NetC48_1: C48.1 C49.1 J14.2 U8.3
NetC50_1: C50.1 L10.1 U9.2 | length 215.9
  Bottom Layer w22: v1(3148.62,2425) 3172.62,2401 3234,2401 3262,2429 v1(3262,2510)
  other v1: 3516,2510 3544,2510 3292,2511 3262,2540 3292,2540 3516,2540 3544,2540
NetC50_2: C50.2 U9.6 | length 64.9
  Top Layer w22: U9.6@3095.87,2487.6 3095.87,2430.51 C50.2@3101.38,2425
NetC52_1: C52.1 C53.1 J16.2 U9.3
NetC54_1: C54.1 F2.1 L12.1 L14.4 L14.@387.01,2318.9
NetC54_2: C54.2 D9.2 D11.2 L14.1 L14.@387.01,2204.72 L15.1
NetC56_1: C56.1 C74.1 T2.7 | length 398.3
  Top Layer w30: T2.7@1417.5,3786.81 1466.81,3786.81 v2(1467,3787)
  Bottom Layer w30: v2(1467,3787) 1467.19,3786.81 1535.19,3786.81 1560,3762 1560,3725 ; C74.1@1600,3691.5 C74.1@1593.5,3691.5 ; 1560,3691.5 1561.5,3691.5 ; 1560,3691.5 C56.1@1525,3691.5 1558.5,3725 1560,3725 ; 1560,3691.5 1560,3725 ; 1560,3691.5 1560,3690 1561.5,3691.5 ; 1560,3725 C74.1@1593.5,3691.5 ; 1561.5,3691.5 C74.1@1593.5,3691.5
NetC57_2: C57.2 R45.1 R46.1 R47.1 R48.1 | length 659.3
  Bottom Layer w25: R48.1@200,3534.25 232.56,3534.25 351.26,3415.55 C57.2@550,3415.55 550,3459.25 ; R45.1@500,3509.25 550,3459.25 ; R46.1@600,3509.25 550,3459.25
  Bottom Layer w30: R47.1@125,3534.25 R48.1@200,3534.25
NetC58_1: C58.1 D9.4 T2.10 | length 1535.6
  Top Layer w30: 1024.99,3786.81 T2.10@1082.5,3786.81
  Top Layer w40: D9.4@775.77,2982.87 775.77,3657.59 904.99,3786.81 1024.99,3786.81
  Bottom Layer w30: C58.1@500,3664.37 500,3706.81 580,3786.81 v2(925,3786.81)
NetC58_2: C58.2 R45.2 | length 44.9
  Bottom Layer w25: R45.2@500,3564.37 C58.2@500,3609.25
NetC59_1: C59.1 D9.3 T2.15 | length 1111.7
  Top Layer w30: 1024.99,3536.81 T2.15@1082.5,3536.81
  Top Layer w40: D9.3@874.2,2982.87 874.2,3482.59 v2(928.41,3536.81) 1024.99,3536.81
  Bottom Layer w30: C59.1@600,3664.37 800.85,3664.37 v2(928.41,3536.81)
NetC59_2: C59.2 R46.2 | length 44.9
  Bottom Layer w25: R46.2@600,3564.37 C59.2@600,3609.25
NetC60_1: C60.1 D11.3 J18.7 J18.8 | length 1331.2
  Top Layer w30: J18.7@317.91,3762.6 358.07,3802.76 J18.8@387.99,3802.76
  Top Layer w40: J18.8@387.99,3802.76 504.06,3802.76 650,3656.81 D11.3@649.21,2982.87
  Bottom Layer w30: C60.1@125,3689.37 125,3731.81 155.79,3762.6 J18.7@317.91,3762.6
NetC60_2: C60.2 R47.2 | length 44.9
  Bottom Layer w30: R47.2@125,3589.37 C60.2@125,3634.25
NetC61_1: C61.1 D11.4 J18.4 J18.5 | length 956.8
  Top Layer w30: J18.5@317.91,3682.28 358.07,3642.13 J18.4@387.99,3642.13
  Top Layer w40: J18.4@387.99,3642.13 469.69,3642.13 550,3561.81 D11.4@550.79,2982.87
  Bottom Layer w30: 225,3689.37 310.83,3689.37 J18.5@317.91,3682.28
NetC61_2: C61.2 R48.2 | length 44.9
  Bottom Layer w30: R48.2@200,3589.37 C61.2@200,3634.25
NetC62_1: C62.1 C66.1 C67.1 C68.1 C72.1 L16.1 L17.1 R50.2 R51.2 U10.3 | length 1304.2
  Top Layer w20: R50.2@746.38,4486.81 R50.2@746.38,4490.43
  Top Layer w30: R50.2@746.38,4490.43 745,4491.81 U10.3@745,4554.53 745,4641.81 796.5,4693.31 v1(875,4693.31) 888.5,4693.31 955,4626.81 1025,4626.81 ; L17.1@1168.5,4461.81 1144.88,4485.43 C72.1@1100,4485.43 1042.13,4543.31 C67.1@1025,4543.31 1025,4596.81 ; L16.1@1168.5,4586.81 1144.88,4610.43 C62.1@1100,4610.43 1041.38,4610.43 ; 1025,4596.81 1025,4626.81 ; 1025,4596.81 1027.76,4596.81 1041.38,4610.43 ; 1025,4626.81 1041.38,4610.43
  Bottom Layer w30: 573.62,4811.81 573.62,4766.73 647.05,4693.31 v1(875,4693.31)
NetC69_1: C69.1 R50.1 R53.2 U10.4 | length 221.5
  Top Layer w20: R50.1@793.62,4486.81 R53.2@876.38,4486.81 C69.1@876.38,4536.81 870,4536.81 852.28,4554.53 U10.4@795,4554.53
NetC75_1: C75.1 C142.1 T2.2 | length 456.9
  Top Layer w30: T2.2@1417.5,3536.81 1466.81,3536.81 v2(1467,3537)
  Bottom Layer w30: v2(1467,3537) 1467.19,3536.81 1521.95,3536.81 1563.76,3495 1563.76,3457.74 ; 1563.76,3421.5 1563.76,3457.74 ; 1563.76,3421.5 C142.1@1600,3421.5 ; 1563.76,3421.5 C75.1@1525,3421.5 1563.5,3460 1563.5,3457.99 1563.76,3457.74 ; 1563.76,3421.5 1563.76,3421.24 1599.74,3421.24 C142.1@1600,3421.5 ; 1563.76,3457.74 C142.1@1600,3421.5
NetC76_1: C76.1 L19.1 U14.2 | length 217.3
  Bottom Layer w22: v1(1975,1076.38) 1961,1062.38 1961,1000 1995,966 v1(2082,966)
  other v1: 2084,752 2119,752 2084,787 2119,787 2082,931 2117,931 2117,966
NetC76_2: C76.2 U14.6 | length 89.9
  Top Layer w22: C76.2@1975,1123.62 2057.09,1123.62 U14.6@2062.6,1129.13
NetC78_2: C78.2 R57.1 R59.2 U14.4 | length 113.9
  Top Layer w22: U14.4@2137.4,1129.13 2142.91,1123.62 C78.2@2199,1123.62 ; v1(2200,1123.62) R59.2@2250,1123.62
NetC79_1: C79.1 C80.1 J22.2 U13.3
NetC83_1: C83.1 C84.1 C85.1 J23.2 R55.1 U14.3 | length 52.1
  Bottom Layer w15: R55.1@2175,951.38 R55.1@2180.12,956.5
  Bottom Layer w30: R55.1@2180.12,956.5 v1(2225,956.5)
NetC87_1: C87.1 C88.1 J26.2 U15.3
NetC90_1: C90.1 C91.1 J28.2 U16.3
NetC93_1: C93.1 C94.1 J30.2 U17.3
NetC97_1: C97.1 J32.2 U19.4
NetC100_1: C100.1 J35.2 U20.4
NetC101_1: C101.1 J37.2 U21.4
NetC103_1: C103.1 J41.2 U22.4
NetC105_1: C105.1 U23.67 | length 302
  Bottom Layer w10: C105.1@1081.5,4136.81 1137.6,4192.92 U23.67@1360.24,4192.92
NetC106_1: C106.1 U23.20 | length 87.6
  Bottom Layer w10: U23.20@1812.01,4526.58 C106.1@1878.74,4526.58
  Bottom Layer w12: C106.1@1878.74,4526.58 C106.1@1893.5,4511.81
NetC108_1: C108.1 U23.66 | length 324.9
  Bottom Layer w10: C108.1@1081.5,4061.81 1192.92,4173.23 U23.66@1360.24,4173.23
NetC112_2: C112.2 R77.2 U23.11 | length 151.9
  Bottom Layer w10: U23.11@1634.84,4526.58 1634.84,4596.97
  Bottom Layer w12: 1634.84,4596.97 1625,4606.81 C112.2@1625,4613.19 1648.62,4636.81 R77.2@1676.38,4636.81
NetC124_2: C124.2 R100.1 R104.2 XTAL1.3 | length 416.3
  Top Layer w6: R100.1@2110.04,3536.81 2050,3536.81 2025,3511.81 2025,3406.81 2043.62,3388.19 C124.2@2075,3388.19 2142.91,3388.19 XTAL1.3@2154.72,3376.38 2154.72,3333.46 R104.2@2176.38,3311.81
NetC127_1: C127.1 R104.1 R105.1 XTAL1.1 | length 455.1
  Top Layer w6: R104.1@2223.62,3311.81 2345,3311.81 2361.81,3328.62 2361.81,3418.19 2344.57,3435.43 C127.1@2325,3435.43 2313.19,3447.24 XTAL1.1@2245.28,3447.24 2239.96,3452.56 R105.1@2239.96,3536.81
NetC130_1: C130.1 J33.2 U26.4
NetC133_1: C133.1 J42.2 U28.4
NetC134_1: C134.1 J38.2 U29.4
NetC136_1: C136.1 J56.2 U30.4
NetC137_1: C137.1 R118.1 | length 103.8
  Top Layer w22: C137.1@473.62,600 R118.1@577.19,600 ; R118.1@577.19,599.81 R118.1@577.38,599.81
NetC137_2: C137.2 U31.6 | length 101.6
  Top Layer w20: C137.2@426.38,600 426.38,653.19 435.79,662.6 U31.6@470.87,662.6
NetC139_1: C139.1 C140.1 J59.2 U31.3
  other v1: 579.13,737.4 573.62,825
NetC141_1: C141.1 R119.1 U31.4 | length 150.4
  Top Layer w20: R119.1@325,726.38 C141.1@375,726.38 410.73,726.38 421.75,737.4 U31.4@470.87,737.4
NetD1_1: D1.1 D1.2 D3.2 R2.1 T1.9 T1.10 | length 110.3
  Bottom Layer w35: v9(1736.22,1540.2) 1762.84,1566.81 D3.2@1835.53,1566.81
NetD7_2: D7.2 D8.1 R27.1 | length 643.3
  Bottom Layer w25: D7.2@1133.07,1271.26 R27.1@1133.07,1340.44 ; D7.2@1134.53,1269.8 1092.2,1269.8 1066,1296 1066,1651.53 D8.1@1164.47,1750
NetD8_2: D8.2 U3.1 | length 89.5
  Bottom Layer w22: D8.2@1025,1735.53 U3.1@1025,1825
NetD9_1: D9.1 D11.1 F2.2
NetD12_2: D12.2 J19.1 U12.1 | length 192.4
  Bottom Layer w10: J19.1@212.4,4260.63 280.87,4260.63 U12.1@300,4241.5 333.66,4241.5 D12.2@378.35,4196.81
NetF1_2: F1.2 J2.1
NetJ3_1: J3.1 R24.2 | length 142.2
  Top Layer w7.8: R24.2@1994.69,3036.81 2045,3036.81 J3.1@2110,3101.81
NetJ5_1: J5.1 R97.1 R103.2 | length 504.3
  Top Layer w20: R97.1@2375,4376.38 R103.2@2425,4376.38 2616.38,4185 J5.1@2800,4185
NetJ5_3: J5.3 LED2_L.2 R123.1 | length 1927.4
  Top Layer w20: LED2_L.2@2475,4493.66 2505,4463.66 2505,4445 2695,4255 2845,4255 2880,4220 2880,4015 2850,3985 J5.3@2800,3985
  Signal Layer 2 w20: v2(2525,4620) 2860,4620 2890,4590 2890,4025 2850,3985 J5.3@2800,3985
  Bottom Layer w20: R123.1@2500,4661.38 2500,4645 v2(2525,4620)
NetJ18_1: J18.1 T2.16 | length 798.3
  Top Layer w30: v2(974.99,3486.81) T2.16@1082.5,3486.81
  Signal Layer 2 w5: J18.1@317.91,3521.65 342.52,3521.65 cw(c342.52,3495.52) 361,3514 376,3499 ccw(c400.14,3523.14) 400.14,3489 720.64,3489 ccw(c720.64,3589.36) 791.61,3518.39 cw(c814.8,3495.2) 814.8,3528 888.13,3528 cw(c888.13,3496.13) 910.64,3518.69 ; 910.67,3518.67 919.56,3509.77 ccw(c974.99,3565.21) v2(974.99,3486.81)
NetJ18_2: J18.2 T2.14 | length 784.8
  Top Layer w30: v2(974.99,3586.81) T2.14@1082.5,3586.81
  Signal Layer 2 w5: J18.2@387.99,3561.81 379.05,3552.87 ccw(c404.29,3527.62) 370.62,3539.49 370.62,3536.33 ccw(c396.54,3536.33) 378.21,3518 386.11,3510.11 ccw(c400.85,3524.85) 400.85,3504 720.64,3504 ccw(c720.64,3589.36) 781,3529 cw(c814.8,3495.2) 814.8,3543 882.11,3543 ccw(c882.11,3583.11) 910.47,3554.75 919.58,3563.86 cw(c974.99,3508.45) v2(974.99,3586.81)
NetJ18_3: J18.3 T2.11 | length 856.6
  Top Layer w30: v2(974.99,3736.81) T2.11@1082.5,3736.81
  Signal Layer 2 w5: J18.3@317.91,3601.97 340.68,3624.73 ccw(c325.41,3640) 347,3640 347,3645.35 cw(c380.45,3645.35) 356.8,3669 cw(c387.88,3637.92) 387.88,3681.88 ccw(c387.88,3713.72) 410.39,3691.19 415.77,3696.58 ; 415.79,3696.6 cw(c442,3670.35) 442,3707.44 689.02,3707.44 ccw(c689.02,3822.44) 770.34,3741.12 795.61,3766.39 cw(c839.18,3722.82) 839.18,3784.44 879.82,3784.44 cw(c879.82,3756.27) 899.74,3776.19 913.75,3762.18 ccw(c974.99,3823.43) 914.49,3761.44 ccw(c974.99,3823.43) v2(974.99,3736.81)
NetJ18_6: J18.6 T2.9 | length 728.8
  Top Layer w30: v2(974.99,3836.81) T2.9@1082.5,3836.81
  Signal Layer 2 w5: J18.6@387.99,3722.44 689.02,3722.44 ccw(c689.02,3822.44) 759.73,3751.73 785,3777 cw(c839.18,3722.82) 839.18,3799.44 884,3799.44 ccw(c884,3842.29) 914.3,3811.99 914.49,3812.19 cw(c973.94,3752.73) 973.94,3836.81 v2(974.99,3836.81)
NetJ19_6: J19.6 J19.7 J19.8 J19.9 J19.10 J19.11 R54.1 | length 72.3
  Bottom Layer w20: J19.7@213.39,4410.24 283.39,4410.24 R54.1@285,4408.62
NetJ48_1: J48.1 R98.2 R99.1 | length 477.2
  Top Layer w20: R98.2@2550,4708.62 R99.1@2600,4708.62 2600,4725 2623,4748 2763,4748 2800,4711 J48.1@2800,4525
NetJ48_3: J48.3 LED0_L.2 R96.1 | length 461.1
  Top Layer w20: R96.1@2700,4661.38 2719.62,4661.38 2735,4646 2735,4516 2712.66,4493.66 LED0_L.2@2675,4493.66 2727,4441.66 2727,4398 J48.3@2800,4325
NetJ49_2: J49.2 R106.1 | length 120.1
  Bottom Layer w12: R106.1@1900,3938.19 1951.38,3938.19 J49.2@2000,3986.81
NetJ51_2: J51.2 R107.1 | length 59.6
  Bottom Layer w7.87: J51.2@2600,4086.81 R107.1@2600,4146.38
NetJ52_2: J52.2 R109.1 | length 59.6
  Bottom Layer w7.87: J52.2@2475,4086.81 R109.1@2475,4146.38
NetJ53_2: J53.2 R110.1 | length 73
  Bottom Layer w7.87: R110.1@2326.38,4150 2326.38,4123.62 2350,4100 J53.2@2350,4086.81
NetL6_1: L6.1 R31.2 U5.2 | length 348.4
  Top Layer w25: U5.2@3354.13,4400 3468.27,4400 L6.1@3471.46,4396.81 ; R31.2@3373.62,4275 3449.41,4275 3473.2,4251.2 3497.44,4275.44 L6.1@3497.44,4361.44
NetL11_1: L11.1 T2.3 | length 263.1
  Top Layer w5: T2.3@1417.5,3586.81 cw(c1417.5,3486.81) 1488.21,3557.52 ccw(c1515.89,3579.26) 1516.99,3544.08 ; T2.3@1442.86,3580 1453,3580 ; 1515.89,3544 1629.38,3544 ccw(c1629.19,3561.81) L11.1@1647,3562
NetL11_2: L11.2 T2.1 | length 290.5
  Top Layer w5: T2.1@1417.5,3486.81 T2.1@1418.68,3486.81 ; L11.2@1647,3509 ccw(c1628.69,3510.69) 1630.38,3529 1517,3529 ccw(c1515.95,3495.24) 1489.39,3516.1 cw(c1418.68,3586.81) 1453.04,3492.9 ; T2.1@1418.68,3486.81 ccw(c1418.68,3586.81) T2.1@1438.87,3488.87 ; T2.1@1418.68,3486.81 1436.81,3486.81 T2.1@1438.87,3488.87 ; T2.1@1438.87,3488.87 ccw(c1418.68,3586.81) 1453.04,3492.9 ; T2.1@1438.87,3488.87 1442.9,3492.9 1453.04,3492.9
NetL13_1: L13.1 T2.8 | length 263.4
  Top Layer w5: T2.8@1417.5,3836.81 cw(c1417.5,3736.81) 1488.21,3807.52 ccw(c1515.9,3829.26) 1516.99,3794.08 ; T2.8@1442.86,3830 1453,3830 ; 1515.9,3794 1629.38,3794 ccw(c1629.19,3811.81) L13.1@1647,3812 ; L13.1@1657.28,3814.57 L13.1@1657.48,3814.37
NetL13_2: L13.2 T2.6 | length 290.5
  Top Layer w5: T2.6@1417.5,3736.81 T2.6@1418.68,3736.81 ; L13.2@1647,3759 ccw(c1628.69,3760.69) 1630.38,3779 1517,3779 ccw(c1515.95,3745.24) 1489.39,3766.1 cw(c1418.68,3836.81) 1453.04,3742.9 ; T2.6@1418.68,3736.81 ccw(c1418.68,3836.81) T2.6@1438.87,3738.87 ; T2.6@1418.68,3736.81 1436.81,3736.81 T2.6@1438.87,3738.87 ; T2.6@1438.87,3738.87 ccw(c1418.68,3836.81) 1453.04,3742.9 ; T2.6@1438.87,3738.87 1442.9,3742.9 1453.04,3742.9
NetL18_1: L18.1 U13.4
NetL20_1: L20.1 R118.2 U31.2
NetL21_1: L21.1 U15.4
NetL22_1: L22.1 U16.4
NetL23_1: L23.1 U17.4
NetLED0_H_1: LED0_H.1 R99.2 | length 96.2
  Top Layer w20: LED0_H.1@2575,4576.34 2576.34,4576.34 2600,4600 R99.2@2600,4661.38
NetLED0_L_1: LED0_L.1 R95.1 | length 95.4
  Top Layer w20: R95.1@2650,4661.38 2650,4601.34 LED0_L.1@2675,4576.34
NetLED2_H_1: LED2_H.1 R97.2 | length 70
  Top Layer w20: R97.2@2375,4423.62 LED2_H.1@2375,4493.66
NetLED2_L_1: LED2_L.1 R122.1 | length 95.4
  Top Layer w20: LED2_L.1@2475,4576.34 2475,4636.38 R122.1@2500,4661.38
NetLoop_1: Loop.1 R14.1 R15.2 | length 209.7
  Top Layer w20: Loop.1@1225,2836.81 1225,2871.81 1284.69,2931.5 R14.1@1325,2931.5 R15.2@1375,2931.5
NetMCU_LEDs_1: MCU_LEDs.1 R70.1 | length 66.1
  Top Layer w12: MCU_LEDs.1@2113.78,4287.4 2125,4298.62 R70.1@2125,4348.82
NetMCU_LEDs_2: MCU_LEDs.2 R69.1 | length 66.1
  Top Layer w12: R69.1@2075,4348.82 2075,4298.62 MCU_LEDs.2@2086.22,4287.4
NetQ1_3: Q1.3 R6.1 | length 253.4
  Bottom Layer w20: Q1.3@2447.24,1411.81 2447.24,1449.57
  Bottom Layer w35: R6.1@2316.14,1561.81 2400,1561.81 2447.24,1514.57 2447.24,1449.57
NetR3_2: R3.2 T1.4 | length 624.9
  Top Layer w30: T1.4@1948.43,2307.58 1948.43,2405.24 1975,2431.81 2140,2431.81 2170,2401.81 2170,2211.81 2199.53,2182.28 R3.2@2250,2182.28
NetR12_2: R12.2 U1.15 | length 158.7
  Top Layer w7.8: R12.2@1505.32,2931.81 1505.32,2911.5 1515,2901.81 1535,2901.81 1569.88,2866.93 U1.15@1625.2,2866.93
NetR13_1: R13.1 U1.8 | length 550.5
  Top Layer w7.8: U1.8@1774.8,2835.43 1833.62,2835.43 1860,2861.81 v2(1900,2861.81)
  Signal Layer 2 w15: v2(1900,2861.81) 1930,2831.81 1930,2746.81 1995,2681.81 v2(1995,2486.81)
NetR17_2: R17.2 U1.16 | length 415.2
  Top Layer w7.8: v7@1520,2876.81 v7(1525,2876.81) 1550.63,2851.18 U1.16@1625.2,2851.18
  Signal Layer 2 w7.8: v7(1525,2876.81) 1591.77,2876.81 1726.77,3011.81 v7(1768.5,3011.81)
NetR18_1: R18.1 U1.20 | length 188.2
  Top Layer w7.8: 1480,2806.81 1505,2781.81 1565,2781.81 1571.38,2788.19 U1.20@1625.2,2788.19
  Top Layer w15: 1480,2806.81 R18.1@1480,2836.81
NetR19_1: R19.1 U1.2 | length 89.5
  Top Layer w7.8: U1.2@1774.8,2740.95 1815.55,2740.95 1819.69,2736.81
  Top Layer w10: 1819.69,2736.81 v2(1850,2706.5)
NetR20_1: R20.1 U2.9 | length 72
  Top Layer w10: R20.1@1250,1321.5 1250,1327.98 1291.43,1369.41 U2.9@1298.35,1369.41
NetR22_1: R22.1 R22.2 R23.2 U1.5 | length 573.9
  Top Layer w7.8: U1.5@1774.8,2788.19 1971.06,2788.19 R23.2@1994.69,2811.81
  Top Layer w15: R23.2@1994.69,2811.81 2021.26,2811.81 R22.2@2121.26,2911.81 2166.54,2957.09 R22.1@2278.74,2957.09
NetR24_1: R24.1 R28.2 U1.10 | length 280.2
  Top Layer w7.8: U1.10@1774.8,2866.93 1815.12,2866.93 1925,2976.81 1945.32,2976.81 R28.2@1955.32,2986.81 R24.1@1955.32,3036.81
NetR25_2: R25.2 R25.3 R26.1 U1.4 | length 595.1
  Top Layer w7.8: U1.4@1774.8,2772.44 1944.69,2772.44 R26.1@1955.32,2761.81
  Top Layer w10: R25.3@2278.47,2616.81 R25.3@2278.74,2616.54
  Top Layer w15: R26.1@1955.32,2761.81 1955.32,2716.5 2010,2661.81 R25.2@2121.26,2661.81 2166.26,2616.81 R25.3@2278.47,2616.81
NetR30_1: R30.1 R32.2 U4.4 | length 114.9
  Top Layer w22: R32.2@3023.62,2000 3023.62,2037.4 ; R30.1@3023.62,2050 3083.27,2050 U4.4@3095.87,2037.4
NetR35_1: R35.1 R37.2 U6.4 | length 127.5
  Top Layer w20: R37.2@3023.62,1475 R35.1@3023.62,1525 3083.27,1525 U6.4@3095.87,1512.4
NetR36_1: R36.1 R38.2 U7.4 | length 127.5
  Top Layer w20: R38.2@3023.62,3950 R36.1@3023.62,4000 3083.27,4000 U7.4@3095.87,3987.4
NetR39_1: R39.1 R40.2 U8.4 | length 127.5
  Top Layer w20: R40.2@3023.62,3125 R39.1@3023.62,3175 3083.27,3175 U8.4@3095.87,3162.4
NetR41_1: R41.1 R42.2 U9.4 | length 127.5
  Top Layer w22: R42.2@3023.62,2525 R41.1@3023.62,2575 3083.27,2575 U9.4@3095.87,2562.4
NetR43_1: R43.1 R125.2 U2.5 | length 116
  Top Layer w10: U2.5@1318.03,1459.96 1318.03,1478.35 1290,1506.38 1299.62,1516 1330.38,1516 R43.1@1340,1506.38
NetR44_1: R44.1 R129.2 U2.6 | length 194.3
  Top Layer w10: R44.1@1175,1561.38 R129.2@1230,1561.38 1261,1530.38 1261,1481 1282.04,1459.96 U2.6@1298.35,1459.96
NetR49_1: R49.1 R52.2 U10.1 | length 160.3
  Top Layer w30: R49.1@525,4613.19 R52.2@575,4613.19 613.62,4613.19 645,4581.81 U10.1@645,4554.53
NetR55_2: R55.2 U14.5 | length 263.3
  Top Layer w15: U14.5@2100,1129.13 v1(2100,1180)
  Bottom Layer w15: v1(2100,1180) 2100,1085 2175,1010 R55.2@2175,998.62
NetR56_1: R56.1 R58.2 U13.1 | length 132.6
  Top Layer w10: U13.1@2695.87,844.69 2701.38,850.2 R58.2@2701.38,925 R56.1@2701.38,975
NetR60_1: R60.1 R61.2 U15.1 | length 132.6
  Top Layer w10: U15.1@3120.87,844.69 3126.38,850.2 R60.1@3126.38,975
NetR62_1: R62.1 R63.2 U16.1 | length 132.6
  Top Layer w10: U16.1@3545.87,844.68 3551.38,850.19 R63.2@3551.38,925 R62.1@3551.38,975
NetR64_1: R64.1 R65.2 U17.1 | length 132.6
  Top Layer w10: U17.1@3970.87,844.69 3976.38,850.2 R65.2@3976.38,925 R64.1@3976.38,975
NetR73_1: R73.1 Y1.1 | length 132.2
  Bottom Layer w10: Y1.1@1050,4350.87 1162.32,4350.87 R73.1@1176.38,4336.81
NetR93_2: R93.2 RESET.1 | length 100.8
  Top Layer w7.87: RESET.1@1233.07,4761.81 1235.04,4759.84 R93.2@1235.04,4661.81
NetR111_1: R111.1 R112.2 U18.3 | length 155.8
  Top Layer w15: R112.2@3573.62,3650 3597.24,3626.38 U18.3@3597.24,3587.4 3661.22,3587.4 R111.1@3675,3573.62
NetR116_1: R116.1 R117.2 U27.3 | length 141.2
  Top Layer w15: R116.1@803.62,865 813.78,875.16 813.78,929.57 852.76,929.57 R117.2@876.38,953.19
NetR120_1: R120.1 R121.1 | length 135.7
  Top Layer w30: R120.1@207.09,800 207.09,807.09 250,850 R121.1@317.91,850
NetR127_2: R127.2 U2.10 | length 49.2
  Top Layer w10: R127.2@1315,1321.5 1318.03,1324.53 U2.10@1318.03,1369.41
NetR128_1: R128.1 R130.2 U2.4 | length 154.5
  Top Layer w8: U2.4@1337.72,1459.96 1337.72,1473.5 1351.02,1486.81 1364.37,1486.81 1390,1512.44 R130.2@1390,1516.38 1412.24,1516.38 R128.1@1445,1483.62
P1.0: R70.2 U23.21 | length 284.6
  Top Layer w12: v1(2002.01,4448.82) 2082.99,4448.82 2125,4406.81 R70.2@2125,4374.8
  Bottom Layer w10: U23.21@1889.77,4448.82 v1(2002.01,4448.82)
P1.1: R69.2 U23.22 | length 220.6
  Top Layer w12: v1(2000,4411.81) 2060,4411.81 2075,4396.81 R69.2@2075,4374.8
  Bottom Layer w10: U23.22@1889.77,4429.14 1952.68,4429.14 1970,4411.81 v1(2000,4411.81)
